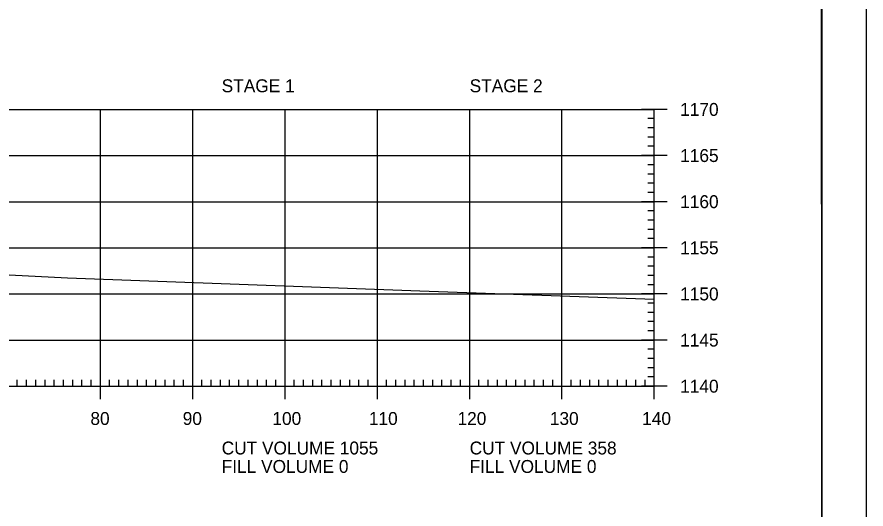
# Model space of a CAD drawing. Extents: x 1322838 to 1324533, y 339903 to 351025.
# Drawn here: x 1323774.7 to 1323866.6, y 341289.8 to 341343.2 of the extents above; entities that cross this region are included whole.
import ezdxf

# ---------------------------------------------------------------- set-up
doc = ezdxf.new("R2010")
doc.units = 0
for name, color, linetype in [('R_Axis', 7, 'Continuous'), ('R_Axis Annot', 7, 'Continuous'), ('R_Border', 7, 'Continuous'), ('R_Exist Surface', 7, 'Continuous'), ('R_Grid', 7, 'Continuous'), ('R_No Plot', 7, 'Continuous')]:
    doc.layers.add(name, color=color, linetype=linetype)

msp = doc.modelspace()

# ---------------------------------------------------------------- linework, layer by layer
at = {"layer": 'R_Axis'}
for p, q in [((1323845.115, 341333.13), (1323842.315, 341333.13)), ((1323843.715, 341303.13), (1323843.715, 341333.13)), ((1323843.715, 341332.13), (1323843.015, 341332.13)), ((1323843.715, 341331.13), (1323843.015, 341331.13)), ((1323843.715, 341330.13), (1323843.015, 341330.13)), ((1323843.715, 341329.13), (1323843.015, 341329.13)), ((1323845.115, 341328.13), (1323842.315, 341328.13)), ((1323843.715, 341327.13), (1323843.015, 341327.13)), ((1323843.715, 341326.13), (1323843.015, 341326.13)), ((1323843.715, 341325.13), (1323843.015, 341325.13)), ((1323843.715, 341324.13), (1323843.015, 341324.13)), ((1323845.115, 341323.13), (1323842.315, 341323.13)), ((1323843.715, 341322.13), (1323843.015, 341322.13)), ((1323843.715, 341321.13), (1323843.015, 341321.13)), ((1323843.715, 341320.13), (1323843.015, 341320.13)), ((1323843.715, 341319.13), (1323843.015, 341319.13)), ((1323845.115, 341318.13), (1323842.315, 341318.13)), ((1323843.715, 341317.13), (1323843.015, 341317.13)), ((1323843.715, 341316.13), (1323843.015, 341316.13)), ((1323843.715, 341315.13), (1323843.015, 341315.13)), ((1323843.715, 341314.13), (1323843.015, 341314.13)), ((1323845.115, 341313.13), (1323842.315, 341313.13)), ((1323843.715, 341312.13), (1323843.015, 341312.13)), ((1323843.715, 341311.13), (1323843.015, 341311.13)), ((1323843.715, 341310.13), (1323843.015, 341310.13)), ((1323843.715, 341309.13), (1323843.015, 341309.13)), ((1323845.115, 341308.13), (1323842.315, 341308.13)), ((1323843.715, 341307.13), (1323843.015, 341307.13)), ((1323843.715, 341306.13), (1323843.015, 341306.13)), ((1323843.715, 341305.13), (1323843.015, 341305.13)), ((1323774.715, 341303.13), (1323774.715, 341303.83)), ((1323775.715, 341303.13), (1323775.715, 341303.83)), ((1323776.715, 341303.13), (1323776.715, 341303.83)), ((1323777.715, 341303.13), (1323777.715, 341303.83)), ((1323778.715, 341303.13), (1323778.715, 341303.83)), ((1323779.715, 341303.13), (1323779.715, 341303.83)), ((1323780.715, 341303.13), (1323780.715, 341303.83)), ((1323781.715, 341303.13), (1323781.715, 341303.83)), ((1323782.715, 341303.13), (1323782.715, 341303.83)), ((1323783.715, 341301.73), (1323783.715, 341304.53)), ((1323784.715, 341303.13), (1323784.715, 341303.83)), ((1323785.715, 341303.13), (1323785.715, 341303.83)), ((1323786.715, 341303.13), (1323786.715, 341303.83)), ((1323787.715, 341303.13), (1323787.715, 341303.83)), ((1323788.715, 341303.13), (1323788.715, 341303.83)), ((1323789.715, 341303.13), (1323789.715, 341303.83)), ((1323790.715, 341303.13), (1323790.715, 341303.83)), ((1323791.715, 341303.13), (1323791.715, 341303.83)), ((1323792.715, 341303.13), (1323792.715, 341303.83)), ((1323793.715, 341301.73), (1323793.715, 341304.53)), ((1323794.715, 341303.13), (1323794.715, 341303.83)), ((1323795.715, 341303.13), (1323795.715, 341303.83)), ((1323796.715, 341303.13), (1323796.715, 341303.83)), ((1323797.715, 341303.13), (1323797.715, 341303.83)), ((1323798.715, 341303.13), (1323798.715, 341303.83)), ((1323799.715, 341303.13), (1323799.715, 341303.83)), ((1323800.715, 341303.13), (1323800.715, 341303.83)), ((1323801.715, 341303.13), (1323801.715, 341303.83)), ((1323802.715, 341303.13), (1323802.715, 341303.83)), ((1323803.715, 341301.73), (1323803.715, 341304.53)), ((1323804.715, 341303.13), (1323804.715, 341303.83)), ((1323805.715, 341303.13), (1323805.715, 341303.83)), ((1323806.715, 341303.13), (1323806.715, 341303.83)), ((1323807.715, 341303.13), (1323807.715, 341303.83)), ((1323808.715, 341303.13), (1323808.715, 341303.83)), ((1323809.715, 341303.13), (1323809.715, 341303.83)), ((1323810.715, 341303.13), (1323810.715, 341303.83)), ((1323811.715, 341303.13), (1323811.715, 341303.83)), ((1323812.715, 341303.13), (1323812.715, 341303.83)), ((1323813.715, 341301.73), (1323813.715, 341304.53)), ((1323814.715, 341303.13), (1323814.715, 341303.83)), ((1323815.715, 341303.13), (1323815.715, 341303.83)), ((1323816.715, 341303.13), (1323816.715, 341303.83)), ((1323817.715, 341303.13), (1323817.715, 341303.83)), ((1323818.715, 341303.13), (1323818.715, 341303.83)), ((1323819.715, 341303.13), (1323819.715, 341303.83)), ((1323820.715, 341303.13), (1323820.715, 341303.83)), ((1323821.715, 341303.13), (1323821.715, 341303.83)), ((1323822.715, 341303.13), (1323822.715, 341303.83)), ((1323823.715, 341301.73), (1323823.715, 341304.53)), ((1323824.715, 341303.13), (1323824.715, 341303.83)), ((1323825.715, 341303.13), (1323825.715, 341303.83)), ((1323826.715, 341303.13), (1323826.715, 341303.83)), ((1323827.715, 341303.13), (1323827.715, 341303.83)), ((1323828.715, 341303.13), (1323828.715, 341303.83)), ((1323829.715, 341303.13), (1323829.715, 341303.83)), ((1323830.715, 341303.13), (1323830.715, 341303.83)), ((1323831.715, 341303.13), (1323831.715, 341303.83)), ((1323832.715, 341303.13), (1323832.715, 341303.83)), ((1323833.715, 341301.73), (1323833.715, 341304.53)), ((1323834.715, 341303.13), (1323834.715, 341303.83)), ((1323835.715, 341303.13), (1323835.715, 341303.83)), ((1323836.715, 341303.13), (1323836.715, 341303.83)), ((1323837.715, 341303.13), (1323837.715, 341303.83)), ((1323838.715, 341303.13), (1323838.715, 341303.83)), ((1323839.715, 341303.13), (1323839.715, 341303.83)), ((1323840.715, 341303.13), (1323840.715, 341303.83)), ((1323841.715, 341303.13), (1323841.715, 341303.83)), ((1323842.715, 341303.13), (1323842.715, 341303.83)), ((1323843.715, 341304.13), (1323843.015, 341304.13)), ((1323843.715, 341301.73), (1323843.715, 341304.53)), ((1323563.715, 341303.13), (1323843.715, 341303.13)), ((1323845.115, 341303.13), (1323842.315, 341303.13))]:
    msp.add_line(p, q, dxfattribs=at)
at = {"layer": 'R_Border'}
msp.add_line((1323861.895, 341187.13), (1323861.895, 341392.59), dxfattribs=at)
at = {"layer": 'R_Exist Surface'}
msp.add_lwpolyline([(1323772.378, 341315.279), (1323780.14, 341314.867), (1323818.317, 341313.469), (1323843.715, 341312.555)], dxfattribs=at)
at = {"layer": 'R_Grid'}
for p, q in [((1323563.715, 341333.13), (1323843.715, 341333.13)), ((1323783.715, 341303.13), (1323783.715, 341333.13)), ((1323793.715, 341303.13), (1323793.715, 341333.13)), ((1323803.715, 341303.13), (1323803.715, 341333.13)), ((1323813.715, 341303.13), (1323813.715, 341333.13)), ((1323823.715, 341303.13), (1323823.715, 341333.13)), ((1323833.715, 341303.13), (1323833.715, 341333.13)), ((1323843.715, 341303.13), (1323843.715, 341333.13)), ((1323563.715, 341328.13), (1323843.715, 341328.13)), ((1323563.715, 341323.13), (1323843.715, 341323.13)), ((1323563.715, 341318.13), (1323843.715, 341318.13)), ((1323563.715, 341313.13), (1323843.715, 341313.13)), ((1323563.715, 341308.13), (1323843.715, 341308.13)), ((1323563.715, 341303.13), (1323843.715, 341303.13))]:
    msp.add_line(p, q, dxfattribs=at)
at = {"layer": 'R_No Plot'}
for points in [[(1323533.308, 341396.485), (1323866.648, 341396.485), (1323866.648, 341183.147), (1323533.308, 341183.147)], [(1323779.635, 341392.59), (1323799.255, 341392.59), (1323799.255, 341382.71), (1323815.368, 341382.71), (1323838.567, 341382.71), (1323838.567, 341350.04), (1323861.775, 341350.04), (1323861.895, 341187.13), (1323545.715, 341187.13), (1323545.715, 341392.59)]]:
    msp.add_lwpolyline(points, close=True, dxfattribs=at)

# ---------------------------------------------------------------- texts
at = {"layer": 'R_Axis Annot'}
for s, p in [('STAGE 1', (1323796.852, 341334.992)), ('STAGE 2', (1323823.715, 341334.992)), ('1170', (1323846.515, 341332.43)), ('1165', (1323846.515, 341327.43)), ('1160', (1323846.515, 341322.43)), ('1155', (1323846.515, 341317.43)), ('1150', (1323846.515, 341312.43)), ('1145', (1323846.515, 341307.43)), ('1140', (1323846.515, 341302.43)), ('80', (1323782.63, 341298.93)), ('90', (1323792.63, 341298.93)), ('100', (1323802.343, 341298.93)), ('110', (1323812.795, 341298.93)), ('120', (1323822.398, 341298.93)), ('130', (1323832.398, 341298.93)), ('140', (1323842.398, 341298.93)), ('CUT VOLUME 1055', (1323796.852, 341295.73)), ('CUT VOLUME 358', (1323823.715, 341295.73)), ('FILL VOLUME 0', (1323796.852, 341293.73)), ('FILL VOLUME 0', (1323823.715, 341293.73))]:
    msp.add_text(s, height=1.4, dxfattribs=at).set_placement(p)

doc.saveas('drawing.dxf')
